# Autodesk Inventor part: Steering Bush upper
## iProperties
Shininess: 20.0
Angle Display Precision: 2
Document Length Units: 11269
Document Angle Units: 11279
Document Time Units: 11290
Document Mass Units: 11283
Document Length Units Precision: 3
Document Angle Units Precision: 2
Compacted: True
Created: 2001-08
Part Number: Steering Bush upper
Document SubType Name: Modeling
Designer: Martin Budgell
Density: 0.0
Volumn: 0.0
Area: 0.0
PropertySet Name: Model Information
Control State: 0
Master: False
Checked Out: False
Author: Martin Budgell
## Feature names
1. Revolution1
2. Extrusion1
3. Extrusion2
4. Fillet1
5. Chamfer1
